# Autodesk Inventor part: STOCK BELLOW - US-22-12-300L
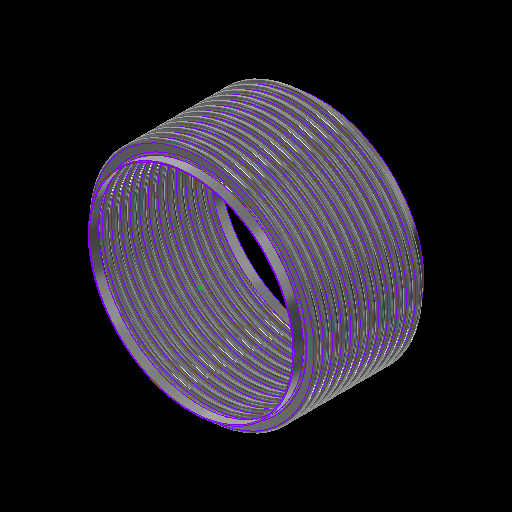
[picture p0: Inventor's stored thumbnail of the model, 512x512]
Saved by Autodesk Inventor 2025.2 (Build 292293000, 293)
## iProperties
Category: 16 GA (0.060 THICK)
RuleStatus: InUse
Created: 2024-01
Part Number: STOCK BELLOW - US-22-12-300L
Project: =STOCK BELLOWS: <Stock Number><SFILL>
Material: ASTM A240-304
Description: =STOCK BELLOWS: <Stock Number>, <SID_> I.D., <SOD_> O.D., <SPLY_> PLY, <Category>, <SNET_CONS> CONS.<PITCH_><STANGENT_> TANGENT<SFILL>
Document SubType Name: Sheet Metal
Designer: GS
Stock Number: U.S-22-12-300L
Surface Area: 37146.4 cm^2
Volume: 5611.91 cm^3
Sheet Metal Rule: Default
Appearance: STAINLESS STEEL
Mass: 45216.8 g
Density: 8.05729 g/cm^3
THK: 0.036
ID: 3.500
OD: 4.250
CONS_: 2
PITCH: 0.500
TANGENT: 0.500
BELLOWS_UPSET: 0.000
d79: 1.000
d82: 1.000
d83: 26.000
d84: 24.000
d174: 8
d214: 8
STHK_: 0.060
SID_: 22.000
SOD_: 24.750
SPITCH_: 1.000
STANGENT__: 1.000
SBELLOWS_UPSET_: 0.000
SDIFF_TAN: 1.000
d252: 2
d275: 2
d287: 0.050
d289: 0.500
d290: 0.000
SOD_NECK: 22 1/4
PLY: 1
PSET: 4.178
PBAR: 1.035
COUNTER: 1.500
NET_TUBE: 3.071
CONS: 2
S_CONS: 0
NET_CONS: 2
ID_M: 88.90 mm
OD_M: 107.95 mm
THK_M: 0.91 mm
ID_U: 3.500 in
OD_U: 4.250 in
THK_U: 0.036 in
TANGENT2: 0.500
TAN_TO_TAN: 1.000 in
d80: 2.571
d81: 10
SID: 2.375
SCONS_: 12
SPITCH: 0.250
STANGENT_: 1.000
SBELLOWS_UPSET: 0.000
SNET_CONS: 12
SS_CONS: 0
SCONS: 8
d190: 8
d191: 1
d192: 1
d193: 8
d194: 0
SIZE: 22.00
PRESSURE: 300
d230: 8
STANGENT: 4.000
SPLY_: 2
d233: 8
d234: 0
d263: 2
d265: 1
d268: 2
d269: 0
d286: 2
d288: 1
d291: 2
d292: 0
SREROLL: 0.750
BLETP: 1.000 ul
PRES_Copy: 85
MATTABLE: 20 GA (0.036 THICK)
PART_NUMBER: U.S-22-12-300L
PITCH_: =, <SPITCH_> PITCH,
CFILL: .
SFILL: .
MESH: ,
COMP: 2.11
EXT: 1.06
LAT: 0.36
ANG: 573
ASR: 6338
LSR: 36072
ANSR: 11623
PRES: 300
COMPM: 21.1
EXTM: 10.55
LATM: 3.60
ASRM: 1109.974
PRESM: 20.684
LSRM: 6317.289
ANSRM: 2035.536
TEMPMIN: 20
TEMPMAX: 800
TEMPMINM: -7
TEMPMAXM: 427
WEIGHTM: 45.217
WEIGHT: 99.686
Author: GS
Keywords: 20 GA (0.036 THICK)
Comments: =STOCK BELLOW - <STOCK NUMBER>
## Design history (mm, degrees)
sketch "Sketch2"
  geometry: L1 (0, -177.245)-(0, 562.856) reference; L2 (45.364, 0)-(44.45, 0); L3 (48.082, -2.718)-(50.343, -2.718); L4 (48.082, -3.632)-(50.343, -3.632); L5 (50.343, -9.982)-(48.082, -9.982); L6 (50.343, -9.068)-(48.082, -9.068); L7 (45.364, -12.7)-(44.45, -12.7); L8 (48.082, 0)-(48.082, -12.7); L9 (50.343, -6.35)-(53.975, -6.35); L10 (44.45, 0)-(44.45, -12.7); L11 (20.376, 102.841)-(20.376, 101.926); L12 (58.262, 457.127)-(58.262, 349.177); L13 (58.262, 444.427)-(58.262, 336.477); L14 (93.133, -58.817)-(93.133, -71.517); L15 (118.746, -66.401)-(118.746, -66.401); L16 (50.343, -9.068)-(50.343, -9.982); L17 (48.082, -9.068)-(48.082, -9.982); L18 (48.082, -9.525)-(50.343, -9.525); L19 (53.975, 0)-(53.975, -12.7); L20 (-50.343, -9.068)-(-50.343, -9.982); L21 (-50.343, -2.718)-(-48.082, -2.718); L22 (-50.343, -3.632)-(-48.082, -3.632); L23 (-48.082, -9.068)-(-50.343, -9.068); L24 (-50.343, -9.525)-(-48.082, -9.525); L25 (-48.082, -9.982)-(-50.343, -9.982); L26 (-48.082, -9.068)-(-48.082, -9.982); L27 (-44.45, 0.653)-(-44.45, -12.047); L28 (-48.082, -6.35)-(-44.45, -6.35); L29 (-50.343, 0.653)-(-50.343, -12.7); L30 (-53.061, 0)-(-53.975, 0); L31 (-53.975, 0)-(-53.975, -12.7); L32 (-53.061, -12.7)-(-53.975, -12.7); A1 r 2.718 centre (48.082, 0) between (45.364, 0) and (48.082, -2.718); A2 r 3.632 centre (48.082, 0) between (44.45, 0) and (48.082, -3.632); A3 r 3.632 centre (50.343, -6.35) between (50.343, -9.982) and (50.343, -2.718); A4 r 2.718 centre (50.343, -6.35) between (50.343, -9.068) and (50.343, -3.632); A5 r 2.718 centre (48.082, -12.7) between (48.082, -9.982) and (45.364, -12.7); A6 r 3.632 centre (48.082, -12.7) between (48.082, -9.068) and (44.45, -12.7); A7 r 3.175 centre (50.343, -6.35) between (50.343, -9.525) and (53.518, -6.35); A8 r 3.175 centre (48.082, -12.7) between (48.082, -9.525) and (44.907, -12.7); A9 r 2.718 centre (-50.343, -12.7) between (-50.343, -9.982) and (-53.061, -12.7); A10 r 2.718 centre (-48.082, -6.35) between (-48.082, -9.068) and (-48.082, -3.632); A11 r 3.175 centre (-48.082, -6.35) between (-48.082, -9.525) and (-44.907, -6.35); A12 r 3.632 centre (-48.082, -6.35) between (-48.082, -9.982) and (-48.082, -2.718); A13 r 3.175 centre (-50.343, -12.7) between (-50.343, -9.525) and (-53.518, -12.7); A14 r 3.632 centre (-50.343, -12.7) between (-50.343, -9.068) and (-53.975, -12.7); A15 r 2.718 centre (-50.343, 0) between (-53.061, 0) and (-50.343, -2.718); A16 r 3.632 centre (-50.343, 0) between (-53.975, 0) and (-50.343, -3.632); 10 further points
  constraints: 62 end point, 38 point on circle, 20 tangent, 16 centre point, 12 parallel, 9 midpoint, 7 vertical, 6 coincident, 6 concentric, 6 point on line, 4 equal radius, 4 perpendicular, 3 horizontal, 1 collinear, 1 horizontal alignment, 10 other
  dimensions: "THK" = 0.9144 distance of L11.start L11.end; "ID" = 88.9 distance of L11.end point (20.376, 13.026); "OD" = 107.95 distance of L12.start L12.end; "PITCH" = 12.7 distance of L12.start L13.start; "TANGENT" = 12.7 distance of L14.start L14.end; "BELLOWS_UPSET" = 0 distance of L15.start L15.end; "d43" = 88.9 diameter of L10 L1 (= ID); "d44" = 107.95 diameter of L9.end L1 (= OD); "d45" = 0.9144 distance between parallel lines of L5 L6 (computed from THK, PLY); "d46" = 3.6322 radius of A3 (computed from PITCH, THK, PLY); "UPSET_PITCH" = 12.7 distance of L2.end L7.end (derived); "SIDEWALL_ANGLE" = 360 deg dimension on L3 L9 (derived); "CON_GAP" = 5.4356 distance of point (48.082, -9.068) point (48.082, -3.632) (derived); "TAN1" = 4.98728 dimension on A8 (derived); "TAN2" = 4.98728 dimension on A7 (derived); "LEG1" = 2.2606 distance of L18.start L18.end (derived); "d278" = 0.9144 distance between parallel lines of L25 L23 (derived); "d279" = 3.6322 radius of A12 (derived); "d280" = 12.7 distance of L30.end L31.end (derived); "d281" = 360 deg dimension on L21 L28 (derived); "d282" = 5.4356 distance of point (-50.343, -9.068) point (-50.343, -3.632) (derived); "d283" = 4.98728 dimension on A13 (derived); "d284" = 4.98728 dimension on A11 (derived); "d285" = 2.2606 distance of L24.start L24.end (derived); "d293" = 88.9 diameter of L27 L1 (derived); "d294" = 107.95 diameter of L31 L1 (derived)
  node "Sketch Rectangular Pattern1" dims "d31" = 25.4, "ID" = 88.9
  node "Sketch Rectangular Pattern2" dims "d39" = 25.4, "PITCH" = 12.7
revolve "CONS" stored, may be unused: angle "d48" = 90 deg
node "BELLOW MIDPLANE"
pattern_linear "Rectangular Pattern2" dims "d52" = 12.7 (= UPSET_PITCH)
sketch "Sketch5"
  geometry: C1 r 45.364 at (0, 0) reference; C2 r 44.45 at (0, 0) reference
extrude "TANGENT" new body sketch "Sketch5" distance "d53" = 12.7 (= TANGENT); taper "d54" = 0 deg
revolve "SAMETAN" stored, may be unused: angle "d65" = 90 deg
revolve "DIFFTAN" stored, may be unused: angle "d70" = 90 deg
sketch "Sketch9"
  geometry: L1 (53.319, 0)-(-53.319, 0) reference; L2 (0, -17.78)-(0, 17.78) reference; L3 (38.085, 0)-(-38.085, 0); L4 (38.085, -11.906)-(38.085, 11.906); L5 (25.385, -11.906)-(25.385, 11.906); L6 (13.15, 11.906)-(13.15, -11.906); L7 (-25.385, -11.906)-(-25.385, 11.906); L8 (-38.085, -11.906)-(-38.085, 11.906); L9 (37.291, -11.906)-(37.291, 11.906); L10 (38.085, -11.906)-(37.291, -11.906); L11 (38.085, 11.906)-(37.291, 11.906); L12 (13.546, 11.906)-(12.753, 11.906); L13 (12.753, 11.906)-(12.753, -11.906); L14 (12.753, -11.906)-(13.546, -11.906); L15 (13.546, -11.906)-(13.546, 11.906); L16 (-13.546, 11.906)-(-13.546, -11.906); L17 (-13.15, 11.906)-(-13.15, -11.906); L18 (-13.546, -11.906)-(-12.753, -11.906); L19 (-12.753, -11.906)-(-12.753, 11.906); L20 (-12.753, 11.906)-(-13.546, 11.906); L21 (-38.085, -11.906)-(-37.291, -11.906); L22 (-37.291, -11.906)-(-37.291, 11.906); L23 (-37.291, 11.906)-(-38.085, 11.906); L24 (-38.085, 11.906)-(-38.085, -11.906); L25 (38.085, -0.397)-(-38.085, -0.397); L26 (-38.085, -0.397)-(-38.085, 0.397); L27 (-38.085, 0.397)-(38.085, 0.397); L28 (38.085, 0.397)-(38.085, -0.397); L29 (-38.085, 11.906)-(38.085, 11.906); L30 (38.085, 11.906)-(38.085, 12.7); L31 (38.085, 12.7)-(-38.085, 12.7); L32 (-38.085, 12.7)-(-38.085, 11.906); L33 (38.085, -11.906)-(-38.085, -11.906); L34 (-38.085, -11.906)-(-38.085, -12.7); L35 (-38.085, -12.7)-(38.085, -12.7); L36 (38.085, -12.7)-(38.085, -11.906); 30 further points
  constraints: 68 end point, 13 midpoint, 13 parallel, 8 horizontal, 7 perpendicular, 6 equal length, 3 point on line, 2 vertical, 14 other
  dimensions: "d115" = 23.8125 distance of L4.start L4.end (derived); "d116" = 12.7 distance between parallel lines of L4 L5 (derived); "d117" = 12.23516 distance between parallel lines of L5 L6 (derived); "d125" = 38.53427 distance between parallel lines of L7 L6 (derived); "d127" = 12.7 distance between parallel lines of L8 L7 (derived); "d128" = 24.93516 distance between parallel lines of L6 L4 (derived); "d130" = 76.16943 distance between parallel lines of L8 L4 (derived); "RULER_THK" = 0.79375 distance between parallel lines of L4 L9; "d135" = 0.79375 distance of L13.end L14.end (derived); "d138" = 26.29911 distance of L13.end L16.end (derived); "d143" = 0.79375 distance of L22.end L8.end (derived); "d144" = 0.79375 distance between parallel lines of L27 L25 (derived)
extrude "RULER" join sketch "Sketch9" distance "d149" = 0.79375 (derived); taper "d150" = 0 deg
extrude "BARS" join sketch "Sketch9" distance "d151" = 0.79375 (derived); taper "d152" = 0 deg
pattern_linear "Rectangular Pattern4" dims "d155" = 26.29911 (derived)
sketch "Sketch13"
  geometry: L1 (93.149, -52.467)-(93.149, -77.867); L2 (282.448, 0)-(279.4, 0); L3 (282.448, -25.4)-(279.4, -25.4); L4 (306.451, -20.574)-(287.274, -20.574); L5 (306.451, -17.526)-(287.274, -17.526); L6 (306.451, -12.7)-(314.325, -12.7); L7 (287.274, -4.826)-(306.451, -4.826); L8 (287.274, 0)-(287.274, -25.4); L9 (279.4, 0)-(279.4, -25.4); L10 (58.254, 132.219)-(58.254, -496.431); L11 (58.254, 106.819)-(58.254, -521.831); L12 (58.254, 56.019)-(58.254, -572.631); L13 (58.254, 30.619)-(58.254, -598.031); L14 (58.254, 5.219)-(58.254, -623.431); L15 (58.254, -20.181)-(58.254, -648.831); L16 (58.254, -45.581)-(58.254, -674.231); L17 (58.254, 81.419)-(58.254, -547.231); L18 (20.376, 103.45)-(20.376, 101.926); L19 (287.274, -7.874)-(306.451, -7.874); L20 (0, -835.521)-(0, 293.509) reference; L21 (-62.865, 0)-(377.19, 0) reference; A1 r 4.826 centre (287.274, 0) between (282.448, 0) and (287.274, -4.826); A2 r 4.826 centre (287.274, -25.4) between (287.274, -20.574) and (282.448, -25.4); A3 r 7.874 centre (287.274, -25.4) between (287.274, -17.526) and (279.4, -25.4); A4 r 4.826 centre (306.451, -12.7) between (306.451, -17.526) and (306.451, -7.874); A5 r 7.874 centre (306.451, -12.7) between (306.451, -20.574) and (306.451, -4.826); A6 r 7.874 centre (287.274, 0) between (279.4, 0) and (287.274, -7.874); 6 further points; 1 other entity
  constraints: 38 end point, 15 point on circle, 9 tangent, 6 centre point, 6 parallel, 5 vertical alignment, 4 point on line, 4 vertical, 3 coincident, 3 concentric, 2 collinear, 2 equal radius, 1 horizontal, 1 perpendicular, 23 other
  dimensions: "SBELLOWS_UPSET_" = 0 distance of point (118.762, -66.401) point (118.762, -66.401); "STOTAL_THK_BELLOW__" = 3.048 distance between parallel lines of L4 L5 (derived); "d224" = 7.874 radius of A5 (derived); "d225" = 25.4 distance of L2.end L3.end (derived); "SSIDEWALL_ANGLE_" = 360 deg dimension on L7 L6 (derived); "SSCON_GAP_" = 9.652 distance of point (287.274, -17.526) point (287.274, -7.874) (derived); "d235" = 558.8 diameter of L9 L20 (derived); "d236" = 628.65 diameter of L6.end L20 (derived)
  node "Sketch Rectangular Pattern4" dims "d228" = 25.4
  node "Sketch Rectangular Pattern5" dims "d229" = 25.4
revolve "SBELLOW" stored, may be unused: angle "d197" = 90 deg
pattern_linear "Rectangular Pattern5" dims "d204" = 25.4 (derived)
revolve "STANGENT" stored, may be unused: angle "d240" = 90 deg
revolve "SSAMETAN" stored, may be unused: angle "d241" = 90 deg
revolve "SDIFFTAN" stored, may be unused: angle "d246" = 90 deg
revolve "INVCON" stored, may be unused: angle "d295" = 90 deg
pattern_linear "Rectangular Pattern6" dims "d298" = 12.7 (derived)
revolve "INVTANGENT" stored, may be unused: angle "d302" = 90 deg
revolve "INVSAMETAN" stored, may be unused: angle "d307" = 90 deg
revolve "INVDIFFTAN" stored, may be unused: angle "d312" = 90 deg
sketch "ID BELLOW MOUNT CALC"
  geometry: L1 (44.45, 0)-(38.1, 0); L2 (38.1, 0)-(38.1, 12.7); L3 (38.1, 12.7)-(44.45, 12.7); L4 (44.45, 12.7)-(44.45, 0); L5 (36.513, 12.7)-(35.598, 12.7); L6 (35.598, 12.7)-(35.598, 0); L7 (35.598, 0)-(36.513, 0); L8 (36.513, 0)-(36.513, 12.7); L9 (0, -2.54)-(0, 15.24) reference; L10 (-8.89, 0)-(53.34, 0) reference; 1 further point
  constraints: 16 end point, 5 parallel, 2 collinear, 2 horizontal, 2 perpendicular
  dimensions: "d314" = 12.7 distance of L5.end L6.end (derived); "d315" = 0.9144 distance of L5.start L5.end (derived); "IG" = 1.5875 distance between parallel lines of L2 L8; "PIPE_OD" = 88.9 diameter of L4 L9; "PIPE_WALL" = 6.35 distance of L2.end L3.end; "ID_MT_BELLOW" = 71.1962 diameter of L6 L9 (derived)
revolve "CFILL" stored, may be unused: angle "d320" = 90 deg
pattern_linear "Rectangular Pattern7" dims "d323" = 12.7 (derived)
revolve "SFILL" stored, may be unused: angle "d324" = 90 deg
pattern_linear "Rectangular Pattern8" dims "d327" = 25.4 (derived)
node "STOCK BELLOW MIDPLANE"
node "BELLOW"
sketch "Sketch6"
  geometry: L1 (-12.7, 45.364)-(0, 45.364); L2 (0, 45.364)-(0, 44.45); L3 (0, 44.45)-(-12.7, 44.45); L4 (-12.7, 44.45)-(-12.7, 45.364); L5 (10.16, 0)-(-60.96, 0) reference; L6 (-38.1, -89.422)-(-38.1, 153.44) reference; 1 further point
  constraints: 8 end point, 2 parallel, 1 horizontal, 1 perpendicular
  dimensions: "d61" = 12.7 distance of L2.end L3.end (derived); "d62" = 0.9144 distance of L1.end L2.end (derived); "d63" = 88.9 diameter of L3 L5 (derived); "d64" = 25.4 distance between parallel lines of L4 L6 (derived)
sketch "Sketch12"
  geometry: 1 further point
sketch "Sketch14"
  geometry: L1 (-25.4, 282.448)-(0, 282.448); L2 (0, 282.448)-(0, 279.4); L3 (0, 279.4)-(-25.4, 279.4); L4 (-25.4, 279.4)-(-25.4, 282.448); L5 (5.08, 0)-(-30.48, 0) reference; L6 (0, -56.49)-(0, 338.938) reference; 1 further point
  constraints: 8 end point, 2 parallel, 1 collinear, 1 horizontal, 1 perpendicular
  dimensions: "d237" = 3.048 distance of L3.end L1.start (derived); "d238" = 558.8 diameter of L3 L5 (derived); "d239" = 25.4 distance of L1.start L1.end (derived); "SOD_NECK" = 564.896 diameter of L1 L5 (derived)
sketch "Sketch15"
  geometry: L1 (-56.49, 0)-(338.938, 0) reference; L2 (279.4, -304.8)-(282.448, -304.8); L3 (282.448, -304.8)-(282.448, -330.2); L4 (282.448, -330.2)-(279.4, -330.2); L5 (279.4, -330.2)-(279.4, -304.8); L6 (0, -398.78)-(0, 81.28) reference; 1 further point
  constraints: 8 end point, 2 parallel, 1 horizontal, 1 perpendicular
  dimensions: "d205" = 25.4 distance of L4.end L2.start (derived); "d206" = 3.048 distance of L3.end L4.end (derived); "d207" = 558.8 diameter of L5 L6 (derived); "d208" = 304.8 distance between parallel lines of L1 L2 (derived)
node "TANGENT_"
node "SAME_TAN"
sketch "Sketch8"
  geometry: L1 (45.364, -25.4)-(44.45, -25.4); L2 (44.45, -25.4)-(44.45, -38.1); L3 (44.45, -38.1)-(45.364, -38.1); L4 (45.364, -38.1)-(45.364, -25.4); L5 (0, -48.26)-(0, 22.86) reference; L6 (-89.422, 0)-(153.44, 0) reference; 1 further point
  constraints: 8 end point, 2 parallel, 1 horizontal, 1 perpendicular
  dimensions: "d66" = 88.9 diameter of L2 L5 (derived); "TOTAL_THK_BELLOW" = 0.9144 distance of L2.end L3.end (derived); "d68" = 25.4 distance between parallel lines of L1 L6 (derived); "d69" = 12.7 distance of L1.end L2.end (derived)
node "DIFF_TAN"
node "Sketch Rectangular Pattern3" dims "d138" = 26.29911 (derived), "d141" = 25.4
node "SBELLOW_"
node "STANGENT_"
node "SSAME_TAN"
sketch "Sketch16"
  geometry: L1 (282.448, -304.8)-(279.4, -304.8); L2 (279.4, -304.8)-(279.4, -330.2); L3 (279.4, -330.2)-(282.448, -330.2); L4 (282.448, -330.2)-(282.448, -304.8); L5 (0, -398.78)-(0, 81.28) reference; L6 (-56.49, 0)-(338.938, 0) reference; 1 further point
  constraints: 8 end point, 2 parallel, 1 horizontal, 1 perpendicular
  dimensions: "SDIFF_TAN" = 25.4 distance of L3.end L1.start; "d243" = 3.048 distance of L2.end L3.end (derived); "d244" = 304.8 distance between parallel lines of L1 L6 (derived); "d245" = 558.8 diameter of L2 L5 (derived)
node "SDIFF_TAN"
body "Solid15"
sketch "Sketch17"
  geometry: L1 (53.975, 12.7)-(53.061, 12.7); L2 (53.061, 12.7)-(53.061, 0); L3 (53.061, 0)-(53.975, 0); L4 (53.975, 0)-(53.975, 12.7); L5 (0, -2.54)-(0, 15.24) reference; L6 (-10.795, 0)-(64.77, 0) reference; 2 further points
  constraints: 8 end point, 2 parallel, 1 horizontal, 1 midpoint, 1 perpendicular, 1 point on line
  dimensions: "INVTANGENT" = 12.7 distance of L3.end L1.start (derived); "d300" = 0.9144 distance of L1.start L1.end (derived); "d301" = 107.95 diameter of L4 L5 (derived)
body "Solid16"
sketch "Sketch18"
  geometry: L1 (53.975, -25.4)-(53.061, -25.4); L2 (53.061, -25.4)-(53.061, -38.1); L3 (53.061, -38.1)-(53.975, -38.1); L4 (53.975, -38.1)-(53.975, -25.4); L5 (-10.795, 0)-(64.77, 0) reference; L6 (0, -48.26)-(0, 22.86) reference; 1 further point
  constraints: 8 end point, 2 parallel, 1 horizontal, 1 perpendicular
  dimensions: "d303" = 25.4 distance between parallel lines of L1 L5 (derived); "d304" = 12.7 distance of L3.end L1.start (derived); "d305" = 0.9144 distance of L2.end L3.end (derived); "d306" = 107.95 diameter of L4 L6 (derived)
body "Solid17"
sketch "Sketch19"
  geometry: L1 (53.975, -25.4)-(53.061, -25.4); L2 (53.061, -25.4)-(53.061, -38.1); L3 (53.061, -38.1)-(53.975, -38.1); L4 (53.975, -38.1)-(53.975, -25.4); L5 (0, -48.26)-(0, 22.86) reference; L6 (-10.795, 0)-(64.77, 0) reference; 1 further point
  constraints: 8 end point, 2 parallel, 1 horizontal, 1 perpendicular
  dimensions: "d308" = 12.7 distance of L1.end L2.end (derived); "d309" = 107.95 diameter of L4 L5 (derived); "d310" = 0.9144 distance of L2.end L3.end (derived); "d311" = 25.4 distance between parallel lines of L1 L6 (derived)
body "Solid18"
body "Solid19"
body "Solid20"
other parameters: "BMPL" = -152.4, "PSET" = 106.1212 (computed from OD, THK, PLY) [user parameter], "PBAR" = 26.29911 (= 0.570796 x PITCH + OD - ID) [user parameter; used in 1 equation term], "COUNTER" = 15 [user parameter], "NET_TUBE" = 77.99823 (computed from CONS_, PBAR, TANGENT) [user parameter], "S_CONS" = 0 [user parameter; used in 1 equation term], "ID_M" = 88.9 (= ID) [user parameter], "OD_M" = 107.95 (= OD) [user parameter], "THK_M" = 0.9144 (= THK) [user parameter], "ID_U" = 88.9 (= ID) [user parameter], "OD_U" = 107.95 (= OD) [user parameter], "THK_U" = 0.9144 (= THK) [user parameter], "D_UNITS" = 0 [user parameter], "TANGENT2" = 12.7 [user parameter], "TAN_TO_TAN" = 25.4 [user parameter], "OD_NECK" = 90.7288 [user parameter], "d79" = 25.4, "d80" = 65.29823 [user parameter], "d82" = 25.4, "d83" = 660.4, "d84" = 609.6, "sa_0" = 4, "FRAME_THK" = 0.79375 [user parameter], "CON_FLAT" = 12.23516 [user parameter], "SID" = 60.325 [user parameter], "SPITCH" = 6.35 [user parameter], "STANGENT_" = 25.4 [user parameter], "SBELLOWS_UPSET" = 0 [user parameter], "SS_CONS" = 0 [user parameter], "STAN_TO_TAN_" = 304.8 [user parameter], "d100" = 3.048 [user parameter], "d191" = 25.4 [user parameter], "d194" = 0 [user parameter], "STANGENT" = 101.6 [user parameter], "d234" = 0 [user parameter], "SUPSET_PITCH_" = 25.4 [user parameter], "d269" = 0 [user parameter], "d287" = 1.27, "d289" = 12.7, "d290" = 0, "d292" = 0 [user parameter], "Thickness" = 3.048 (derived), "KFactor" = 4.4, "BendRadius" = 3.048 (derived), "BendReliefWidth" = 3.048 (derived), "BendReliefDepth" = 1.524 (derived), "CornerReliefSize" = 12.192 (derived), "SeamGap" = 0.00508, "MinimumRemnant" = 6.096 (derived), "TransitionRadius" = 3.048 (derived), "JacobiRadiusSize" = 3.048 (derived), "GapSize" = 3.048 (derived), "SREROLL" = 19.05 [user parameter], "CUR_STK_PITCH" = 25.4 [user parameter], "d328" = -152.4 (derived), "ASR" = 63380 [user parameter], "LSR" = 360720 [user parameter], "ANSR" = 116230 [user parameter], "BLETP" = 1 [user parameter], "ASRM" = 11099.7394 [user parameter], "PRESM" = 206.83949 [user parameter], "LSRM" = 63172.8936 [user parameter], "ANSRM" = 20355.3599 [user parameter], "TEMPMIN" = 2664.83333 [user parameter], "TEMPMAX" = 6998.16667 [user parameter], "TEMPMINM" = 2664.83333 [user parameter], "TEMPMAXM" = 6998.16667 [user parameter], "WEIGHT" = 452.16802 [user parameter], "WEIGHTM" = 0.45217 [user parameter]
